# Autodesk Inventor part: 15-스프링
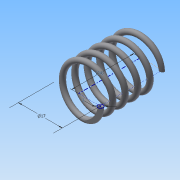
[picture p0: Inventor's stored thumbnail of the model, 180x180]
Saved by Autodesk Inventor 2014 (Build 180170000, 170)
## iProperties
Created: 2016-01
Part Number: 15-스프링
Material: 강철, 탄소
Document SubType Name: Modeling
Designer: Administrator
Density: 7.87 g/cm^3
Appearance: 반연마
Mass: 6.46669 g
Surface Area: 16.7182 cm^2
Volume: 0.821689 cm^3
Author: Administrator
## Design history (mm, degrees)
sketch "스케치1"
  geometry: L1 (0, 0)-(8.5, 0); L2 (8.5, 0)-(8.5, 20.5); L3 (8.5, 20.5)-(0, 20.5); L4 (0, 20.5)-(0, 0); C1 r 1 at (8.5, 0)
  constraints: 8 end point, 2 parallel, 1 centre point, 1 coincident, 1 horizontal, 1 perpendicular
  dimensions: "d0" = 17 diameter of L2 L4; "d1" = 20.5 distance of L3.end L1.start (derived); "d2" = 2 diameter of C1
feature "코일1" sketch "스케치1" pitch "d3" = 10; turns "d5" = 5; dims "d4" = 20.5 (= d1), "d6" = 0, angle "d7" = 90 deg, angle "d8" = 90 deg, "d9" = 0, "d10" = 0
node "작업 평면1"
sketch "스케치2"
  geometry: L1 (-9.5, 0)-(-7.5, 0) reference; 1 further point
  constraints: 1 horizontal alignment
extrude "돌출1" cut sketch "스케치2" stored distance "d12" = 10; taper "d13" = 0 deg
node "작업 평면2"
sketch "스케치3"
  geometry: L1 (-7.5, 0)-(-9.5, 0) reference; 1 further point
  constraints: 1 horizontal alignment
extrude "돌출2" cut sketch "스케치3" stored distance "d15" = 10; taper "d16" = 0 deg
node "솔리드1"
node "절단 모서리 투영1"
node "절단 모서리 투영2"
other parameters: "d11" = 0, "d14" = 20.5 (= d1)
